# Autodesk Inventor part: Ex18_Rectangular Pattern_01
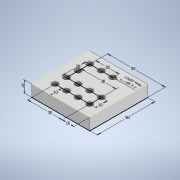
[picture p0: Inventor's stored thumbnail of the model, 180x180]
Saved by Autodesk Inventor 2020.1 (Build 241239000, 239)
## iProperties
Created: 2019-11
Part Number: Ex18_Rectangular Pattern_01
Material: Generic
Document SubType Name: Modeling
Designer: Synergysoft Dell02
Density: 1 g/cm^3
Appearance: Default
Author: Synergysoft Dell02
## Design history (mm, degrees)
node "Annotations"
  node "Hole Note 1" dims "d0" = 50, "d20" = 10
  node "Linear Dimension 1" dims "d0" = 50, "d20" = 10, "d29" = 10 (derived)
sketch "Sketch1"
  geometry: L1 (25, 25)-(-25, 25); L2 (-25, 25)-(-25, -25); L3 (-25, -25)-(25, -25); L4 (25, -25)-(25, 25); L5 (25, 25)-(-25, -25); L6 (-25, 25)-(25, -25); 1 further point
  constraints: 12 end point, 2 midpoint, 2 parallel, 1 horizontal, 1 perpendicular
  dimensions: "d0" = 50 distance of L3.end L2.end; "d1" = 50 distance of L2.end L1.end
extrude "Extrusion1" new body sketch "Sketch1" distance "d2" = 10; taper "d3" = 0 deg
sketch "Sketch2"
  geometry: L1 (-15, -15)-(15, -15); L2 (15, -15)-(15, -5); L3 (15, -5)-(-15, -5); L4 (-15, -5)-(-15, 15); L5 (-15, 15)-(5, 15); L6 (-25, -25)-(25, -25) reference; L7 (25, -25)-(25, 25) reference; L8 (-25, 25)-(-25, -25) reference; 1 further point
  constraints: 10 end point, 4 perpendicular, 1 horizontal
  dimensions: "d4" = 10 distance between parallel lines of L6 L1; "d5" = 10 distance of L1.end L2.end; "d6" = 20 distance of L3.end L4.end; "d7" = 20 distance of L4.end L5.end; "d8" = 30 distance of L1.start L1.end; "d9" = 10 distance between parallel lines of L7 L2; "d26" = 30 distance of L2.end L3.end
hole "Hole1" sketch "Sketch2" diameter "d11" = 3; stored, may be unused: countersink angle "d15" = 90 deg, drill point angle "d17" = 118 deg; dims "d12" = 6, "d13" = 5, "d14" = 2, "d16" = 30
pattern_linear "Rectangular Pattern1" dims "d20" = 10, "d23" = 10
pattern_linear "Rectangular Pattern2"
workplane "Work Plane1"
body "Solid1"
other parameters: "d27" = 62.71645 (derived), "d30" = 46.03237 (derived), "d31" = 46.03237 (derived), "d32" = 53.48655 (derived)
